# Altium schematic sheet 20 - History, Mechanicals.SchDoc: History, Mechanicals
size A3; PageSetup: Record=PageOptions¦CenterHorizontal=True¦CenterVertical=True¦PrintScale=1.01¦XCorrection=1.00¦YCorrection=1.00¦PrintKind=0¦BorderSize=5000000¦LeftOffset=0¦BottomOffset=0¦Orientation=2¦PaperLength=4200¦PaperWidth=2970¦Scale=100¦PaperSource=15¦PrintQuality=600¦MediaType=1¦DitherType=10¦PrintScaleMode=1¦PaperKind=A3¦PaperIndex=8; Author: Juan Anzola; SheetNumber: 20; SheetTotal: 20
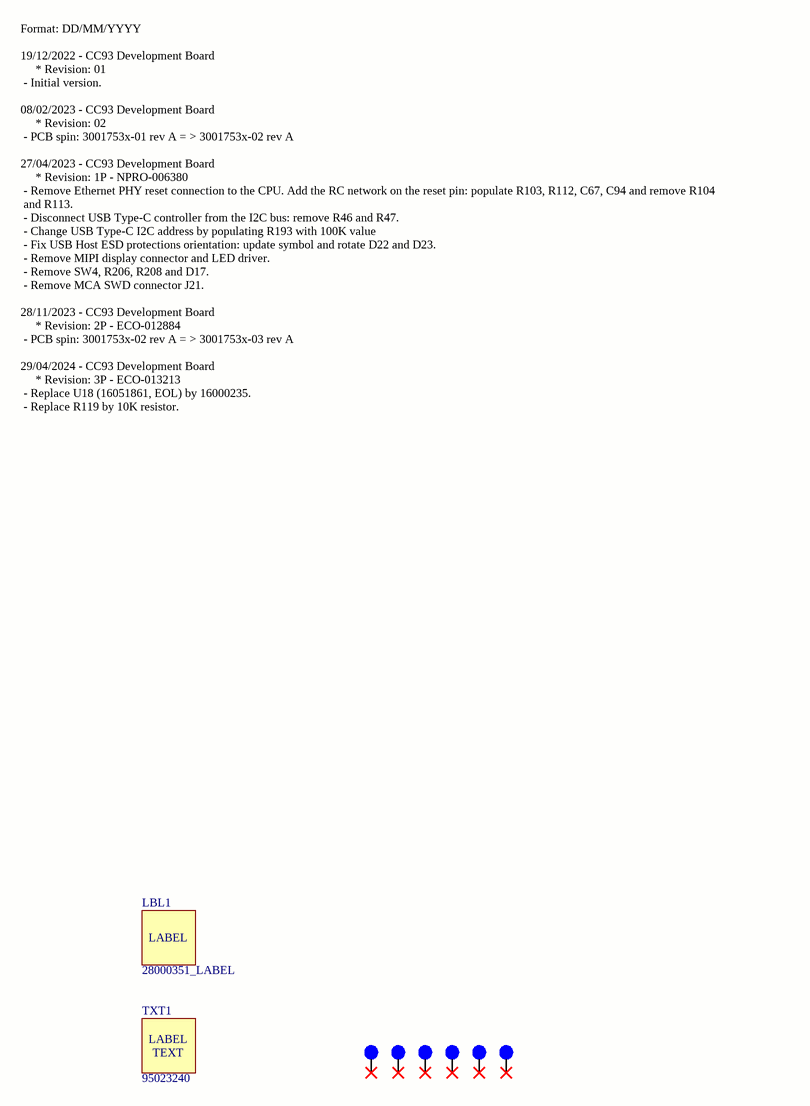
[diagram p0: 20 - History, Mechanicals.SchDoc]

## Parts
FIDUCIAL1  40mil FID  [fiducial_40mil_round]  (value not drawn)  (no BOM)
FIDUCIAL2  40mil FID  [fiducial_40mil_round]  (value not drawn)  (no BOM)
FIDUCIAL3  40mil FID  [fiducial_40mil_round]  (value not drawn)  (no BOM)
FIDUCIAL4  40mil FID  [fiducial_40mil_round]  (value not drawn)  (no BOM)
FIDUCIAL5  40mil FID  [fiducial_40mil_round]  (value not drawn)  (no BOM)
FIDUCIAL6  40mil FID  [fiducial_40mil_round]  (value not drawn)  (no BOM)
LBL1  28000351_LABEL
TXT1  95023240  (mechanical)

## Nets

Not connected (* = marked no-connect by the designer): FIDUCIAL1 1(Fid_1)*; FIDUCIAL2 1(Fid_1)*; FIDUCIAL3 1(Fid_1)*; FIDUCIAL4 1(Fid_1)*; FIDUCIAL5 1(Fid_1)*; FIDUCIAL6 1(Fid_1)*

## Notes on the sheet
- Format: DD/MM/YYYY
  19/12/2022 - CC93 Development Board
  * Revision: 01
  - Initial version.
  08/02/2023 - CC93 Development Board
  * Revision: 02
  - PCB spin: 3001753x-01 rev A = > 3001753x-02 rev A
  27/04/2023 - CC93 Development Board
  * Revision: 1P - NPRO-006380
  - Remove Ethernet PHY reset connection to the CPU. Add the RC network on the reset pin: populate R103, R112, C67, C94 and remove R104
  and R113.
  - Disconnect USB Type-C controller from the I2C bus: remove R46 and R47.
  - Change USB Type-C I2C address by populating R193 with 100K value
  - Fix USB Host ESD protections orientation: update symbol and rotate D22 and D23.
  - Remove MIPI display connector and LED driver.
  - Remove SW4, R206, R208 and D17.
  - Remove MCA SWD connector J21.
  28/11/2023 - CC93 Development Board
  * Revision: 2P - ECO-012884
  - PCB spin: 3001753x-02 rev A = > 3001753x-03 rev A
  29/04/2024 - CC93 Development Board
  * Revision: 3P - ECO-013213
  - Replace U18 (16051861, EOL) by 16000235.
  - Replace R119 by 10K resistor.

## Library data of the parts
FIDUCIAL1-FIDUCIAL6 = CAD0023: 40 Mil Round Fiducial; Part_Type: Mechanical; Component_Life_Cycle_State: Reviewed; Area: 1; Project: SDR Prototype RF Board
LBL1 = 1002170: LBL,Poly White Blank 0.40x0.40; Manufacturer: 3M; Manufacturer_Part_Number: TAAE-014000; Noplace: False; Component_Life_Cycle_State: Created; Area: 100; Project: CCWMX6_SBC board
TXT1 = CAD0111: LBL,.5x.75" 55002179-01 CC93 DVK; Part_Type: Label; Noplace: False; Component_Life_Cycle_State: Pending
